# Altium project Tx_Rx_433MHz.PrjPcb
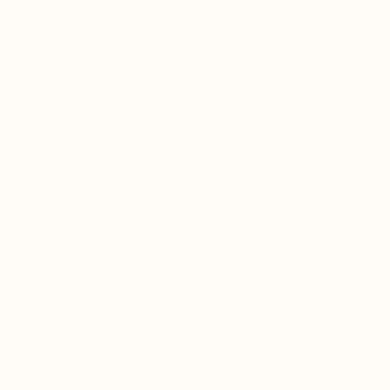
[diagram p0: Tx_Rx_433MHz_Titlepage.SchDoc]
YEAR: 2025; SCH_DOC_VER: 1.0; SCH_AUTHOR: SnLe; PCB_REV: 1A; PCB_ID: 0019-01234; PCB_DOC_VER: 1.0; PCB_AUTHOR: ScSt; PCA_REV: 1A; PCA_NAME: Tx Rx 433MHz Practise Project; PCA_ID: 0029-01234; CLASSIFICATION: Company Confidential
4 sheets, 85 parts. Net scope: global (net labels, ports and power ports of the same name join across sheets).
Board files: Tx_Rx_433MHz.PcbDoc, Tx_Rx_433MHz-Placed.PcbDoc, Tx_Rx_433MHz-Routed.PcbDoc
Sheets:
  Tx_Rx_433MHz_Titlepage.SchDoc
    Top Level = Tx_Rx_433MHz_Block_diagram.SchDoc
      RX = RX.SchDoc
      TX = TX.SchDoc

## Sheet Tx_Rx_433MHz_Titlepage.SchDoc
size A2; SheetNumber: 1; SheetTotal: 4; APPROVED: Yes; Border_Classification: ?; CmpIndex: 0; ENGINEER: KuRe/SnLe; REVIEWED: Yes; REVISION: 2.0; SymIndex: 0; SHEET_SIZE: A2; SHEET02_TITLE: Block Diagram; SHEET03_TITLE: RX; SHEET04_TITLE: TX; SHEET01_TITLE: Title Page; SHEET01_PAGE: 1; SHEET02_PAGE: 2; SHEET03_PAGE: 3; SHEET04_PAGE: 4

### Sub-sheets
Top Level = Tx_Rx_433MHz_Block_diagram.SchDoc: no entries

## Sheet Tx_Rx_433MHz_Block_diagram.SchDoc
size A2; SheetNumber: 1; SheetTotal: 4; APPROVED: Yes; Border_Classification: ?; CmpIndex: 1; ENGINEER: KuRe/SnLe; REVIEWED: Yes; REVISION: 2.0; SymIndex: 1; SHEET_SIZE: A2
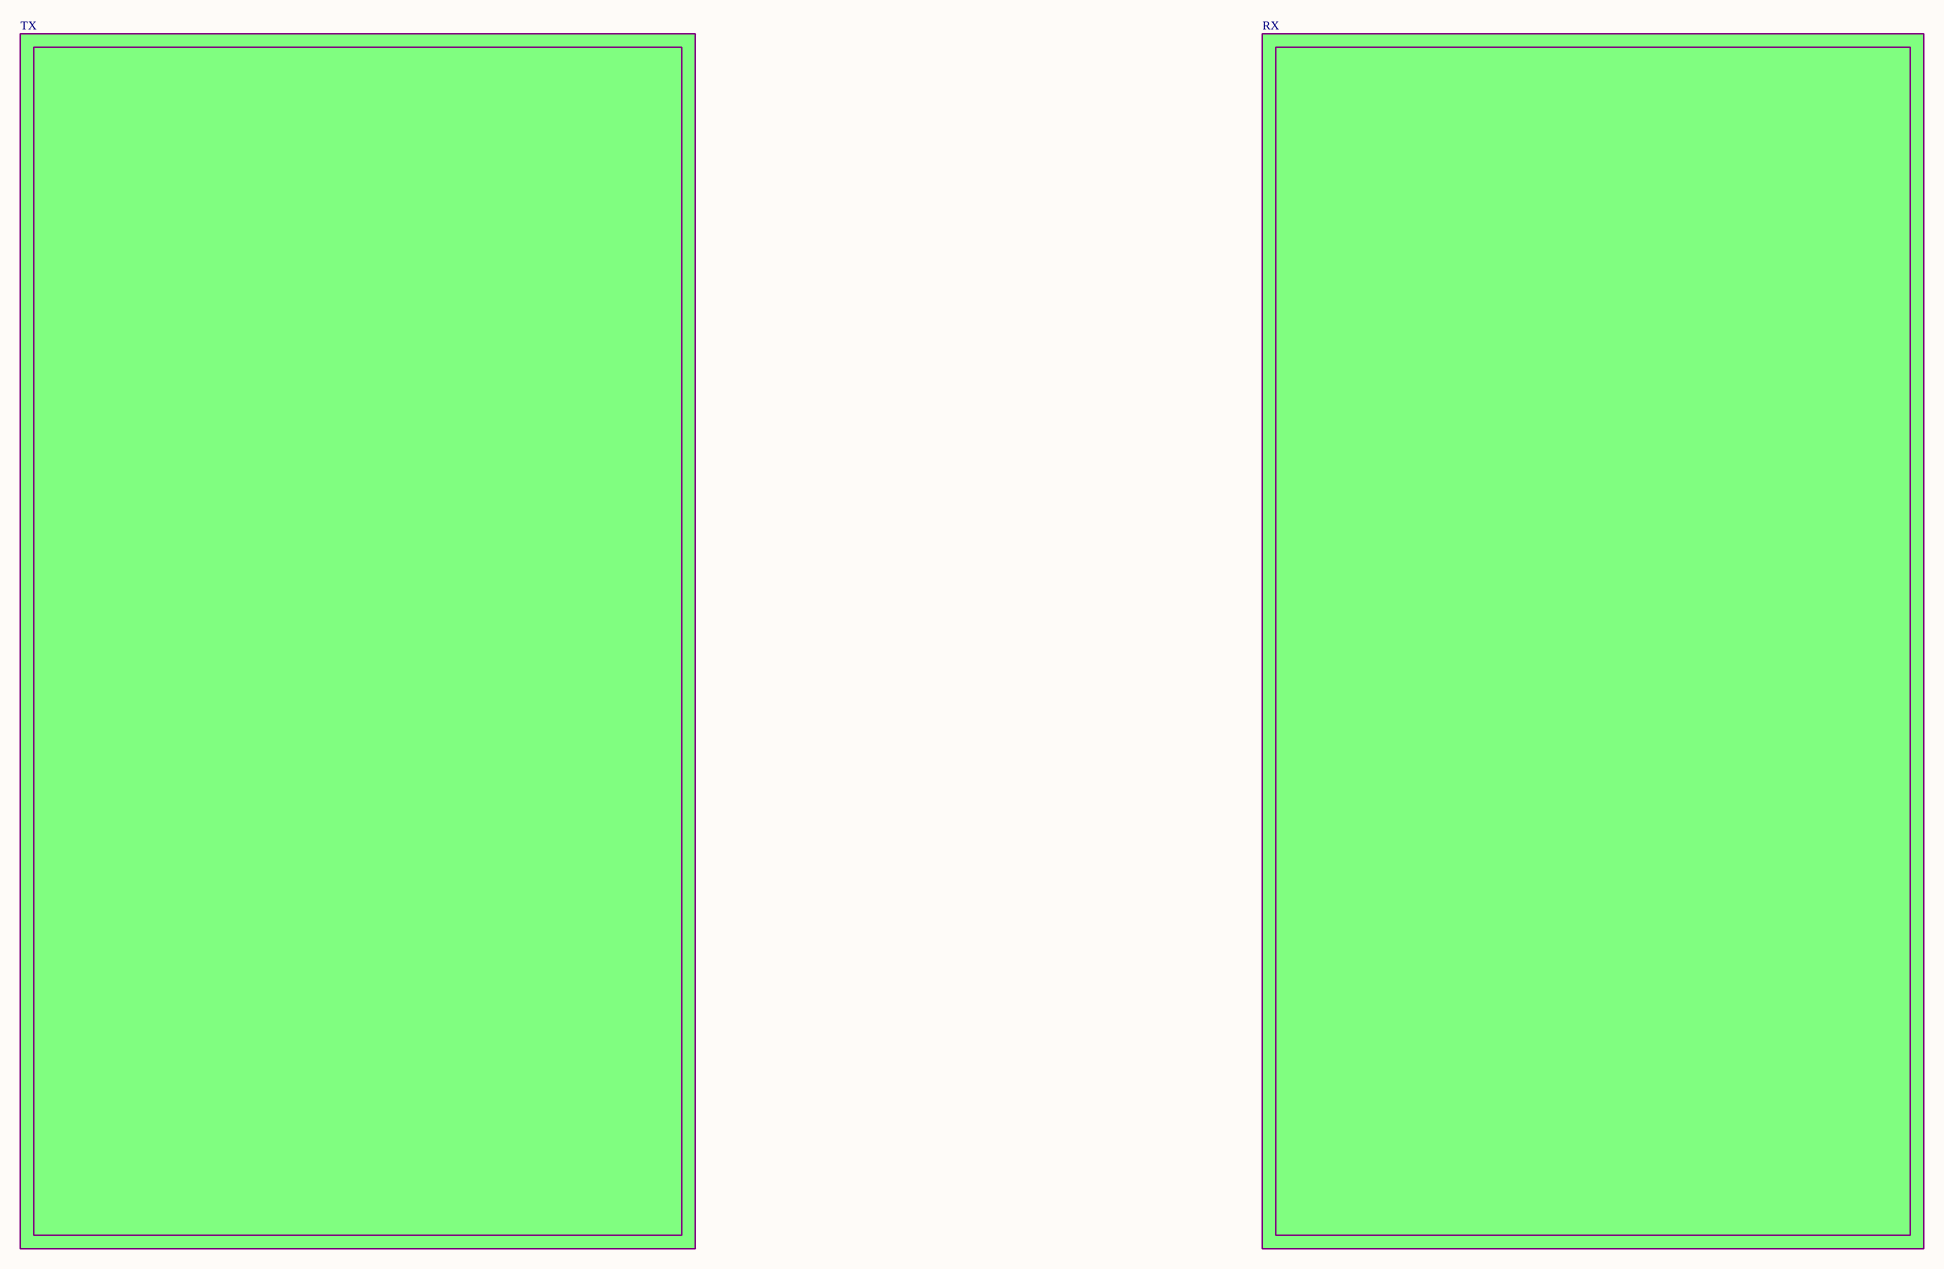
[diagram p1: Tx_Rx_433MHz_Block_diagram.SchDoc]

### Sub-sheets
RX = RX.SchDoc: no entries  | CmpIndex: 3; Name: RX; RefDes Renumber: Refresh; RefDes Start: 200; SymIndex: 6
TX = TX.SchDoc: no entries  | CmpIndex: 2; Name: TX; RefDes Renumber: Refresh; RefDes Start: 100; SymIndex: 4

## Sheet RX.SchDoc
size A2; SheetNumber: 2; SheetTotal: 4; APPROVED: Yes; Border_Classification: ?; CmpIndex: 0; ENGINEER: KuRe/SnLe; REVIEWED: Yes; REVISION: 2.0; SymIndex: 1; SHEET_SIZE: A2
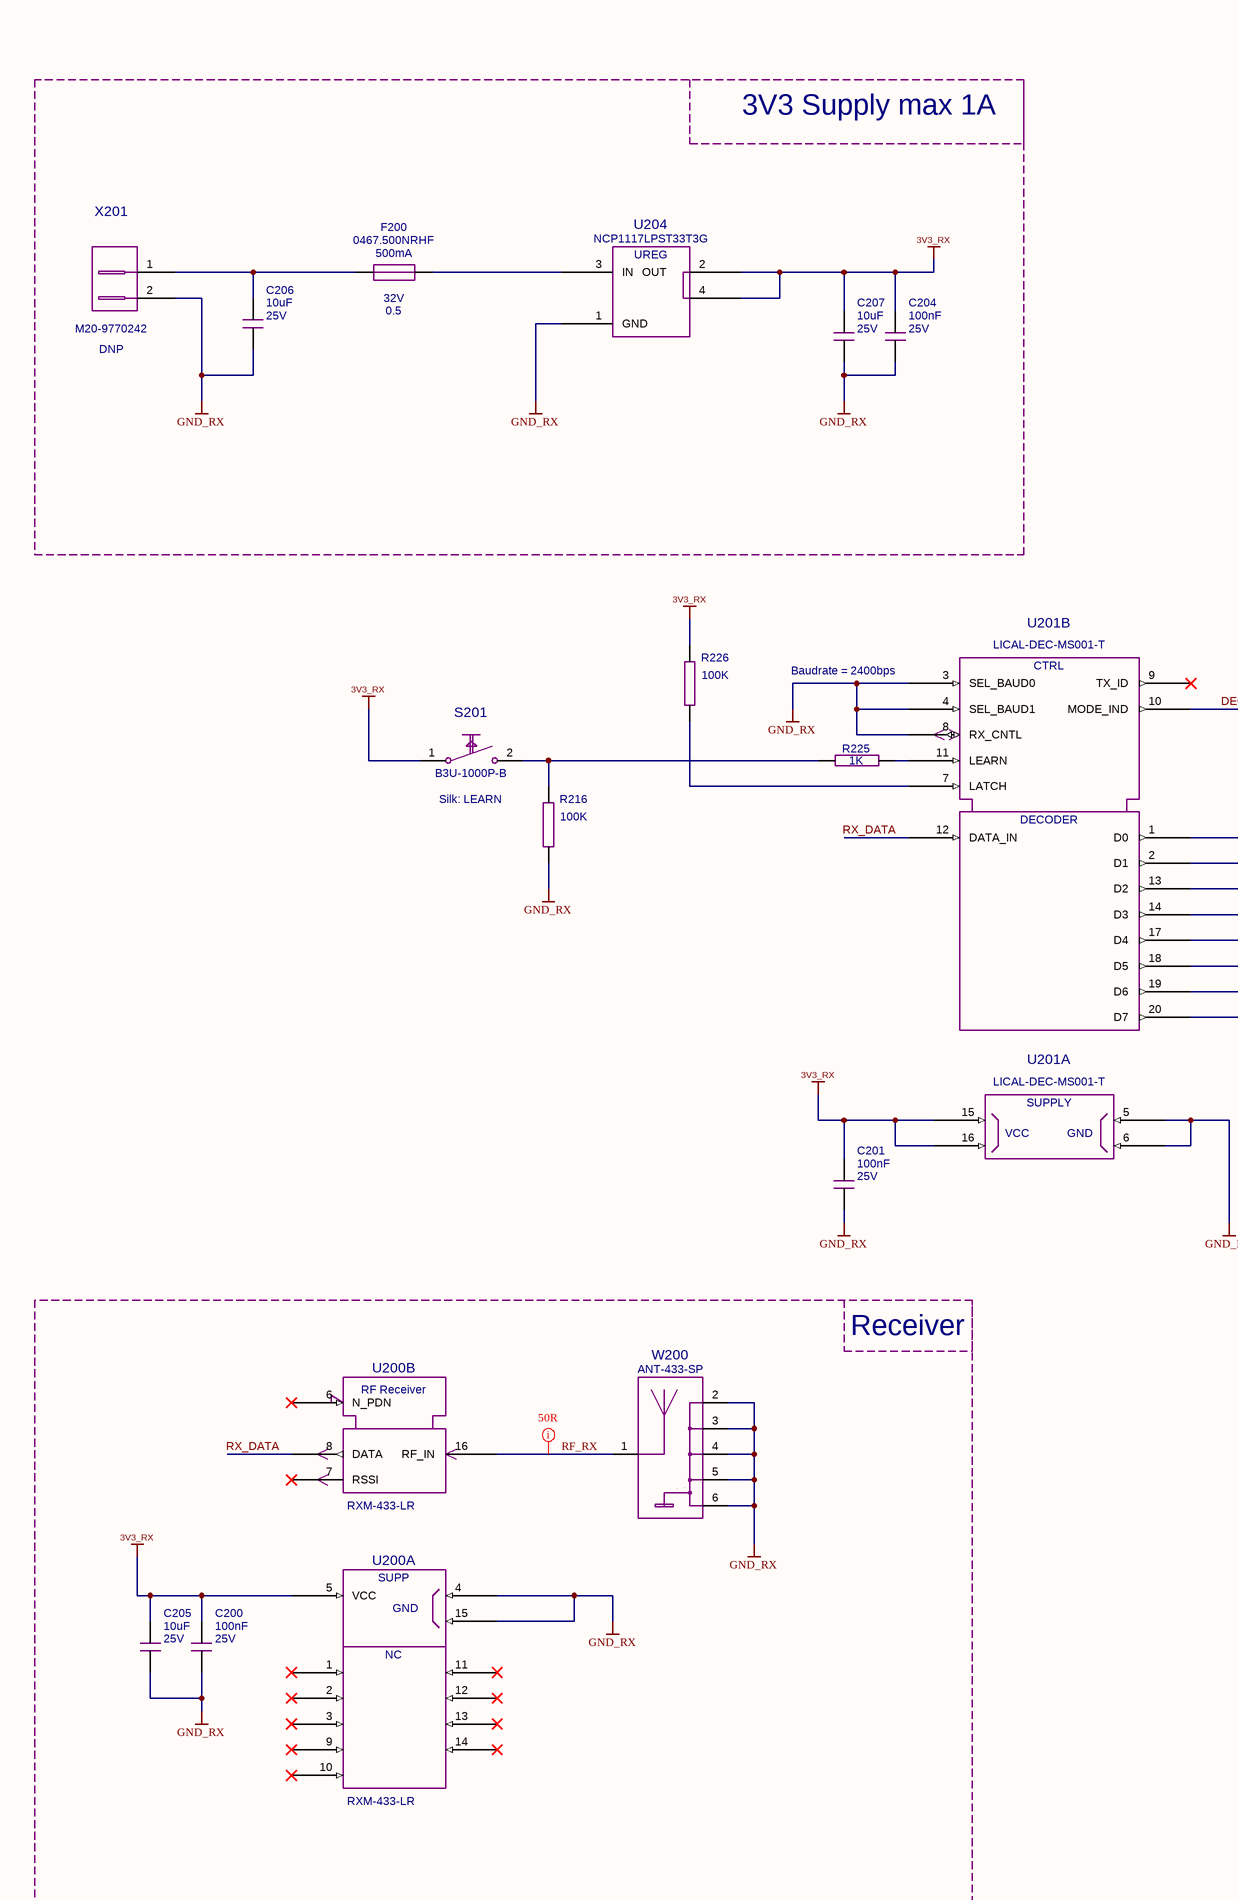
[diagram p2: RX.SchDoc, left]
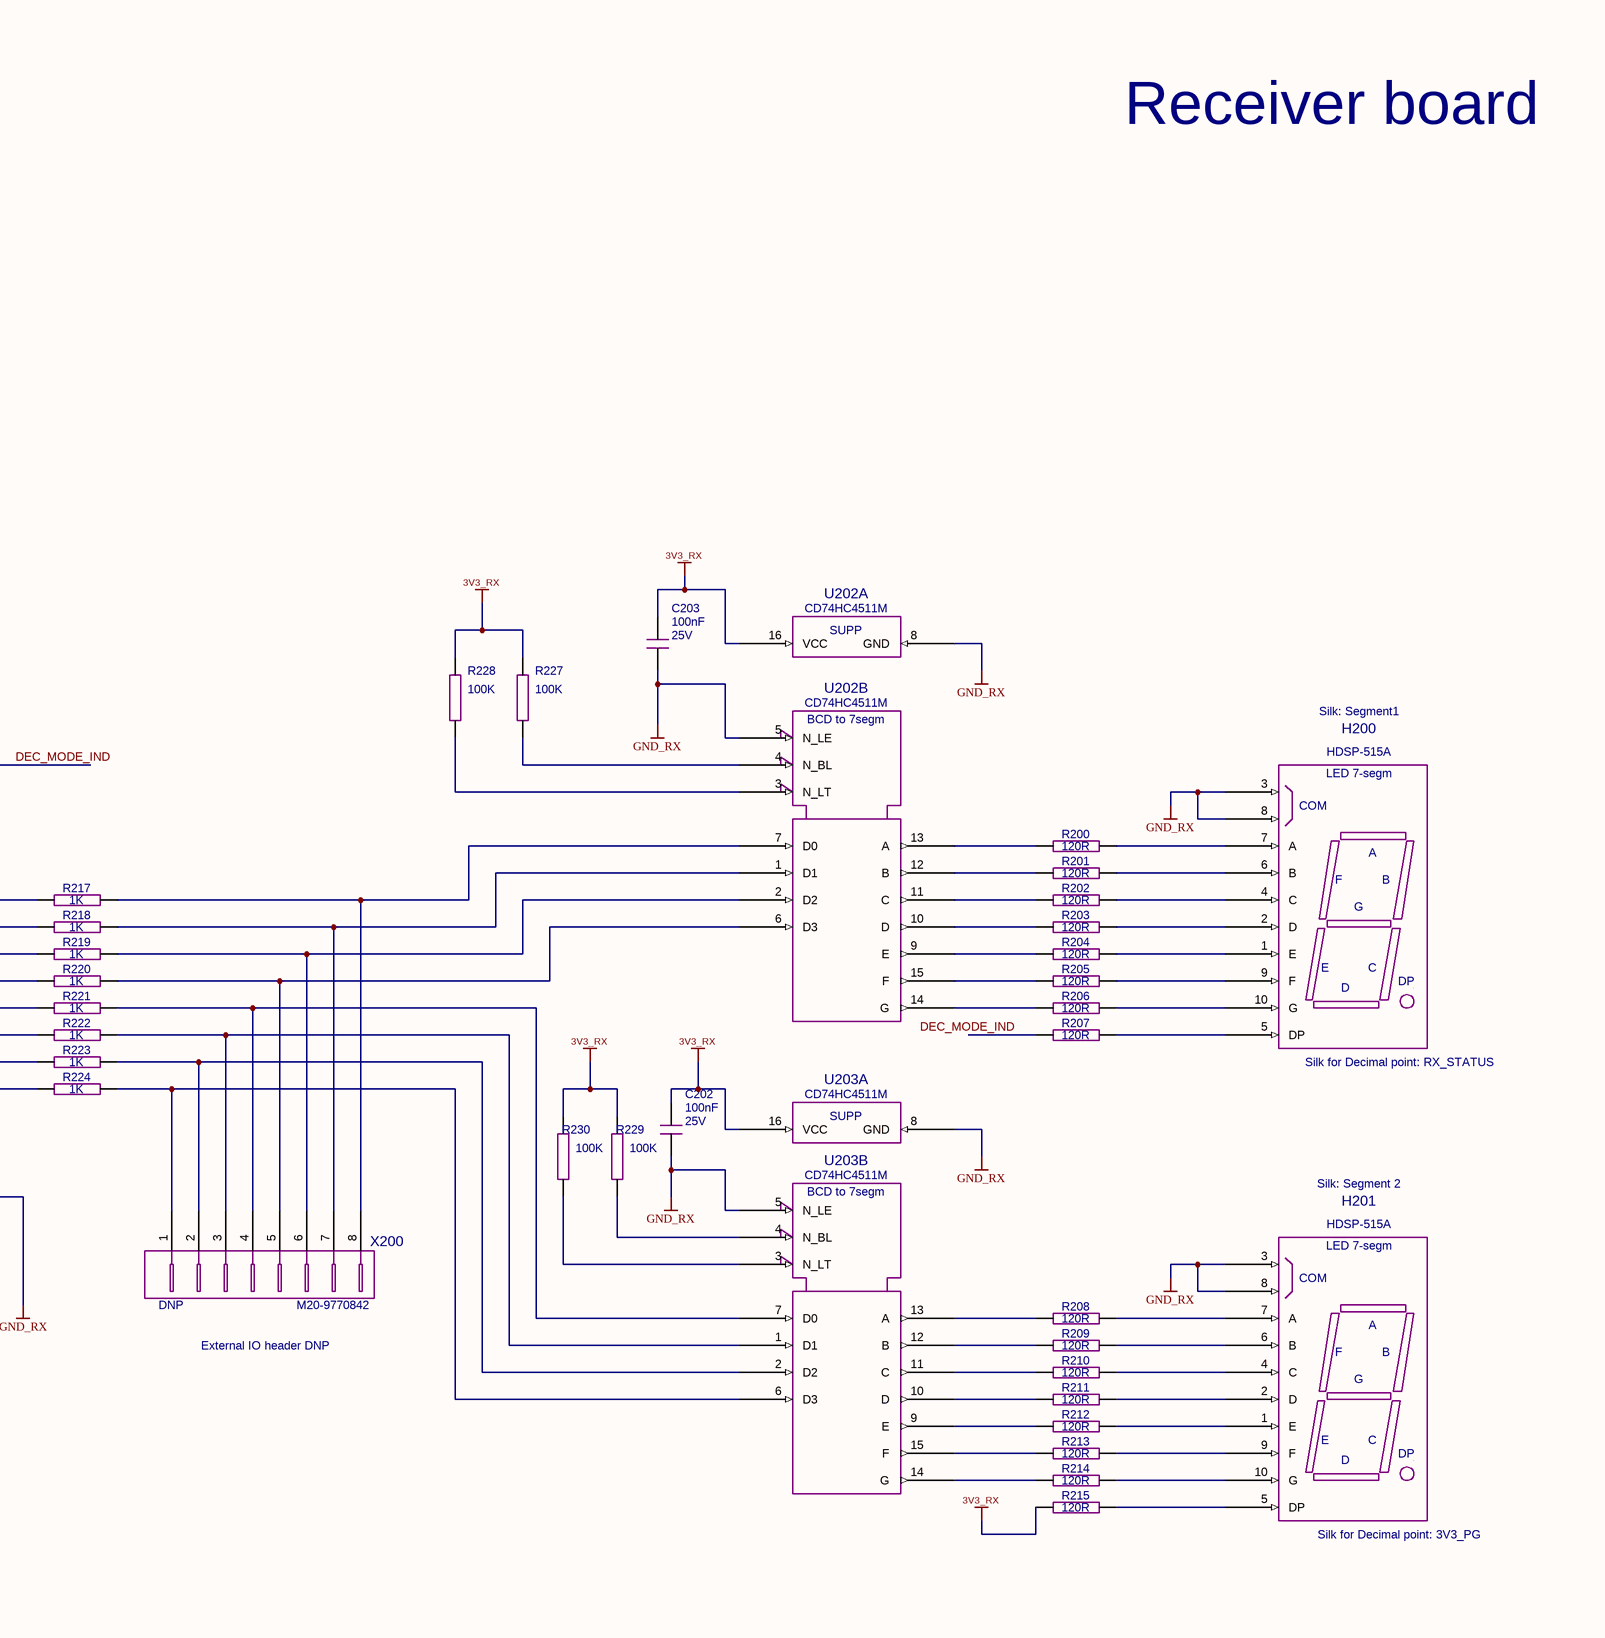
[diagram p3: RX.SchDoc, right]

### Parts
C200  value 100nF  Voltage: 25V  [CAPC1608X90N_0603_GENERIC]  (hidden comment: C_0603_1608X90_GENERIC)
C201  value 100nF  Voltage: 25V  [CAPC1608X90N_0603_GENERIC]  (hidden comment: C_0603_1608X90_GENERIC)
C202  value 100nF  Voltage: 25V  [CAPC1608X90N_0603_GENERIC]  (hidden comment: C_0603_1608X90_GENERIC)
C203  value 100nF  Voltage: 25V  [CAPC1608X90N_0603_GENERIC]  (hidden comment: C_0603_1608X90_GENERIC)
C204  value 100nF  Voltage: 25V  [CAPC1608X90N_0603_GENERIC]  (hidden comment: C_0603_1608X90_GENERIC)
C205  value 10uF  Voltage: 25V  [CAPC3216X190N_1206_GENERIC]  (hidden comment: C_1206_3216X190_GENERIC)
C206  value 10uF  Voltage: 25V  [CAPC2013X140N_AVX]  (hidden comment: 08051C104KAZ2A)
C207  value 10uF  Voltage: 25V  [CAPC2013X140N_AVX]  (hidden comment: 08051C104KAZ2A)
F200  value 500mA  Current: 0.5  MPN: 0467.500NRHF  Voltage: 32V  [RESC1608X60N_0603_GENERIC]  (hidden comment: 0467XXXX)
H200  MPN: HDSP-515A  [BROADCOM_HDSP-5XXX]  (hidden comment: HDSP-5XXX)
H201  MPN: HDSP-515A  [BROADCOM_HDSP-5XXX]  (hidden comment: HDSP-5XXX)
R200  value 120R  [RESC2012X60N_0805_GENERIC]  (hidden comment: R_0805_2012X60_GENERIC)
R201  value 120R  [RESC2012X60N_0805_GENERIC]  (hidden comment: R_0805_2012X60_GENERIC)
R202  value 120R  [RESC2012X60N_0805_GENERIC]  (hidden comment: R_0805_2012X60_GENERIC)
R203  value 120R  [RESC2012X60N_0805_GENERIC]  (hidden comment: R_0805_2012X60_GENERIC)
R204  value 120R  [RESC2012X60N_0805_GENERIC]  (hidden comment: R_0805_2012X60_GENERIC)
R205  value 120R  [RESC2012X60N_0805_GENERIC]  (hidden comment: R_0805_2012X60_GENERIC)
R206  value 120R  [RESC2012X60N_0805_GENERIC]  (hidden comment: R_0805_2012X60_GENERIC)
R207  value 120R  [RESC2012X60N_0805_GENERIC]  (hidden comment: R_0805_2012X60_GENERIC)
R208  value 120R  [RESC2012X60N_0805_GENERIC]  (hidden comment: R_0805_2012X60_GENERIC)
R209  value 120R  [RESC2012X60N_0805_GENERIC]  (hidden comment: R_0805_2012X60_GENERIC)
R210  value 120R  [RESC2012X60N_0805_GENERIC]  (hidden comment: R_0805_2012X60_GENERIC)
R211  value 120R  [RESC2012X60N_0805_GENERIC]  (hidden comment: R_0805_2012X60_GENERIC)
R212  value 120R  [RESC2012X60N_0805_GENERIC]  (hidden comment: R_0805_2012X60_GENERIC)
R213  value 120R  [RESC2012X60N_0805_GENERIC]  (hidden comment: R_0805_2012X60_GENERIC)
R214  value 120R  [RESC2012X60N_0805_GENERIC]  (hidden comment: R_0805_2012X60_GENERIC)
R215  value 120R  [RESC2012X60N_0805_GENERIC]  (hidden comment: R_0805_2012X60_GENERIC)
R216  value 100K  [RESC2012X60N_0805_GENERIC]  (hidden comment: R_0805_2012X60_GENERIC)
R217  value 1K  [RESC2012X60N_0805_GENERIC]  (hidden comment: R_0805_2012X60_GENERIC)
R218  value 1K  [RESC2012X60N_0805_GENERIC]  (hidden comment: R_0805_2012X60_GENERIC)
R219  value 1K  [RESC2012X60N_0805_GENERIC]  (hidden comment: R_0805_2012X60_GENERIC)
R220  value 1K  [RESC2012X60N_0805_GENERIC]  (hidden comment: R_0805_2012X60_GENERIC)
R221  value 1K  [RESC2012X60N_0805_GENERIC]  (hidden comment: R_0805_2012X60_GENERIC)
R222  value 1K  [RESC2012X60N_0805_GENERIC]  (hidden comment: R_0805_2012X60_GENERIC)
R223  value 1K  [RESC2012X60N_0805_GENERIC]  (hidden comment: R_0805_2012X60_GENERIC)
R224  value 1K  [RESC2012X60N_0805_GENERIC]  (hidden comment: R_0805_2012X60_GENERIC)
R225  value 1K  [RESC2012X60N_0805_GENERIC]  (hidden comment: R_0805_2012X60_GENERIC)
R226  value 100K  [RESC2012X60N_0805_GENERIC]  (hidden comment: R_0805_2012X60_GENERIC)
R227  value 100K  [RESC2012X60N_0805_GENERIC]  (hidden comment: R_0805_2012X60_GENERIC)
R228  value 100K  [RESC2012X60N_0805_GENERIC]  (hidden comment: R_0805_2012X60_GENERIC)
R229  value 100K  [RESC2012X60N_0805_GENERIC]  (hidden comment: R_0805_2012X60_GENERIC)
R230  value 100K  [RESC2012X60N_0805_GENERIC]  (hidden comment: R_0805_2012X60_GENERIC)
S201  MPN: B3U-1000P-B  [OMRON_B3U_1000P_B]  (hidden comment: B3U_1000P_B)
U200  RXM-433-LR  [LINX_RXM-433-LR]  (parts A,B of 2)
U201  MPN: LICAL-DEC-MS001-T  [SOP65P780X200-20N]  (hidden comment: LICAL-DEC-MS001)  (parts A,B of 2)
U202  CD74HC4511M  [SOIC127P600X175-16N]  (parts A,B of 2)
U203  CD74HC4511M  [SOIC127P600X175-16N]  (parts A,B of 2)
U204  MPN: NCP1117LPST33T3G  [SOT230P700X180-4N]  (hidden comment: LM1117MPX)
W200  ANT-433-SP  [LINX_ANT-433-SP]
X200  MPN: M20-9770842  Place: DNP  [HARWIN_M20_9770842]  (hidden comment: M20_9770842)
X201  MPN: M20-9770242  Place: DNP  [HARWIN_M20_9770242]  (hidden comment: M20_9770242)

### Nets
3V3_RX: C200.1(P) C201.1(P) C202.1(P) C203.1(P) C204.1(P) C205.1(P) C207.1(P) R215.1(P) R226.2(M) R227.2(M) R228.2(M) R229.2(M) R230.2(M) S201.1(S1) U200.5(VCC) U201.15(VCC1) U201.16(VCC2) U202.16(VCC) U203.16(VCC) U204.2(OUT) U204.4(TAB)
GND_RX: C200.2(M) C201.2(M) C202.2(M) C203.2(M) C204.2(M) C205.2(M) C206.2(M) C207.2(M) H200.3(COM1) H200.8(COM2) H201.3(COM1) H201.8(COM2) R216.1(P) U200.4(GND1) U200.15(GND2) U201.3(SEL_BAUD0) U201.4(SEL_BAUD1) U201.5(GND1) U201.6(GND2) U201.8(RX_CNTL) U202.5(N_LE) U202.8(GND) U203.5(N_LE) U203.8(GND) U204.1(GND) W200.2(GND1) W200.3(GND2) W200.4(GND3) W200.5(GND4) W200.6(GND5) X201.2(P2)
DEC_MODE_IND: R207.1(P) U201.10(MODE_IND)
RF_RX: U200.16(RF_IN) W200.1(ANT)
RX_DATA: U200.8(DATA) U201.12(DATA_IN)
NetC206_1: C206.1(P) F200.1(A) X201.1(P1)
NetF200_2: F200.2(B) U204.3(IN)
NetH200_1: H200.1(E) R204.2(M)
NetH200_2: H200.2(D) R203.2(M)
NetH200_4: H200.4(C) R202.2(M)
NetH200_5: H200.5(DP) R207.2(M)
NetH200_6: H200.6(B) R201.2(M)
NetH200_7: H200.7(A) R200.2(M)
NetH200_9: H200.9(F) R205.2(M)
NetH200_10: H200.10(G) R206.2(M)
NetH201_1: H201.1(E) R212.2(M)
NetH201_2: H201.2(D) R211.2(M)
NetH201_4: H201.4(C) R210.2(M)
NetH201_5: H201.5(DP) R215.2(M)
NetH201_6: H201.6(B) R209.2(M)
NetH201_7: H201.7(A) R208.2(M)
NetH201_9: H201.9(F) R213.2(M)
NetH201_10: H201.10(G) R214.2(M)
NetR200_1: R200.1(P) U202.13(A)
NetR201_1: R201.1(P) U202.12(B)
NetR202_1: R202.1(P) U202.11(C)
NetR203_1: R203.1(P) U202.10(D)
NetR204_1: R204.1(P) U202.9(E)
NetR205_1: R205.1(P) U202.15(F)
NetR206_1: R206.1(P) U202.14(G)
NetR208_1: R208.1(P) U203.13(A)
NetR209_1: R209.1(P) U203.12(B)
NetR210_1: R210.1(P) U203.11(C)
NetR211_1: R211.1(P) U203.10(D)
NetR212_1: R212.1(P) U203.9(E)
NetR213_1: R213.1(P) U203.15(F)
NetR214_1: R214.1(P) U203.14(G)
NetR216_2: R216.2(M) R225.1(P) S201.2(S2)
NetR217_1: R217.1(P) U201.1(D0)
NetR217_2: R217.2(M) U202.7(D0) X200.8(P8)
NetR218_1: R218.1(P) U201.2(D1)
NetR218_2: R218.2(M) U202.1(D1) X200.7(P7)
NetR219_1: R219.1(P) U201.13(D2)
NetR219_2: R219.2(M) U202.2(D2) X200.6(P6)
NetR220_1: R220.1(P) U201.14(D3)
NetR220_2: R220.2(M) U202.6(D3) X200.5(P5)
NetR221_1: R221.1(P) U201.17(D4)
NetR221_2: R221.2(M) U203.7(D0) X200.4(P4)
NetR222_1: R222.1(P) U201.18(D5)
NetR222_2: R222.2(M) U203.1(D1) X200.3(P3)
NetR223_1: R223.1(P) U201.19(D6)
NetR223_2: R223.2(M) U203.2(D2) X200.2(P2)
NetR224_1: R224.1(P) U201.20(D7)
NetR224_2: R224.2(M) U203.6(D3) X200.1(P1)
NetR225_2: R225.2(M) U201.11(LEARN)
NetR226_1: R226.1(P) U201.7(LATCH)
NetR227_1: R227.1(P) U202.4(N_BL)
NetR228_1: R228.1(P) U202.3(N_LT)
NetR229_1: R229.1(P) U203.4(N_BL)
NetR230_1: R230.1(P) U203.3(N_LT)

Not connected (* = marked no-connect by the designer): U200 1(NC1)* 2(NC2)* 3(NC3)* 6(N_PDN)* 7(RSSI)* 9(NC4)* 10(NC5)* 11(NC6)* 12(NC7)* 13(NC8)* 14(NC9)*; U201 9(TX_ID)*

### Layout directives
net class 50R: RF_RX

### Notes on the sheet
- 3V3 Supply max 1A
- Receiver board
- Baudrate = 2400bps
- Silk: Segment1
- Silk: LEARN
- (near H200) Silk for Decimal point: RX_STATUS
- Silk: Segment 2
- External IO header DNP
- Receiver
- (near H201) Silk for Decimal point: 3V3_PG

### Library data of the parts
C200 = C_0603_1608X90_GENERIC: 100nF 25V 10%; Manufacturer: MURATA; MPN: GRM188R71E104KA01D; Part Name: Ceramic chip capacitor 0603-1608x90, generic; Parts: 1; Capacitance: 100000; CmpIndex: 30; Dielectric: X7R; DXDB_LIBNAME: Capacitor; Level: STD; Ref Designator: C200; SymIndex: 23; Tolerance: 10; Type: Ceramic; Valid: -1
C201 = C_0603_1608X90_GENERIC: 100nF 25V 10%; Manufacturer: MURATA; MPN: GRM188R71E104KA01D; Part Name: Ceramic chip capacitor 0603-1608x90, generic; Parts: 1; Capacitance: 100000; CmpIndex: 52; Dielectric: X7R; DXDB_LIBNAME: Capacitor; Level: STD; Ref Designator: C201; SymIndex: 23; Tolerance: 10; Type: Ceramic; Valid: -1
C202 = C_0603_1608X90_GENERIC: 100nF 25V 10%; Manufacturer: MURATA; MPN: GRM188R71E104KA01D; Part Name: Ceramic chip capacitor 0603-1608x90, generic; Parts: 1; Capacitance: 100000; CmpIndex: 80; Dielectric: X7R; DXDB_LIBNAME: Capacitor; Level: STD; Ref Designator: C202; SymIndex: 23; Tolerance: 10; Type: Ceramic; Valid: -1
C203 = C_0603_1608X90_GENERIC: 100nF 25V 10%; Manufacturer: MURATA; MPN: GRM188R71E104KA01D; Part Name: Ceramic chip capacitor 0603-1608x90, generic; Parts: 1; Capacitance: 100000; CmpIndex: 81; Dielectric: X7R; DXDB_LIBNAME: Capacitor; Level: STD; Ref Designator: C203; SymIndex: 23; Tolerance: 10; Type: Ceramic; Valid: -1
C204 = C_0603_1608X90_GENERIC: 100nF 25V 10%; Manufacturer: MURATA; MPN: GRM188R71E104KA01D; Part Name: Ceramic chip capacitor 0603-1608x90, generic; Parts: 1; Capacitance: 100000; CmpIndex: 16; Dielectric: X7R; DXDB_LIBNAME: Capacitor; Level: STD; Ref Designator: C204; SymIndex: 23; Tolerance: 10; Type: Ceramic; Valid: -1
C205 = C_1206_3216X190_GENERIC: 10uF 25V 10%; Manufacturer: AVX; MPN: 12063C106KAT2A; Part Name: Cheramic chip capacitor 1206-3216x190, generic; Parts: 1; Capacitance: 10000000; CmpIndex: 33; Dielectric: X7R; DXDB_LIBNAME: Capacitor; Level: STD; Max Temp: +125; Min Temp: -55; Ref Designator: C205; SymIndex: 23; Tolerance: 10; Type: Ceramic; Valid: -1
C206 = 08051C104KAZ2A: 10uF 25V 10%; Manufacturer: AVX; MPN: 08053D106KAT2A; Part Name: 0805 chip 100nF 10% 100V X7R; Parts: 1; Capacitance: 10000000; CmpIndex: 12; Dielectric: X5R; DXDB_LIBNAME: Capacitor; Level: STD; Ref Designator: C206; SymIndex: 23; Tolerance: 10; Type: Ceramic; Valid: 0
C207 = 08051C104KAZ2A: 10uF 25V 10%; Manufacturer: AVX; MPN: 08053D106KAT2A; Part Name: 0805 chip 100nF 10% 100V X7R; Parts: 1; Capacitance: 10000000; CmpIndex: 15; Dielectric: X5R; DXDB_LIBNAME: Capacitor; Level: STD; Ref Designator: C207; SymIndex: 23; Tolerance: 10; Type: Ceramic; Valid: 0
F200 = 0467XXXX: Thin film 0603 fuse very fast acting; Manufacturer: LITTELFUSE; Part Name: Thin film 0603 very fast acting; CmpIndex: 18; Level: STD; Max Temp: +90; Min Temp: -55; Ref Designator: F200; SymIndex: 25; Valid: -1
H200 = HDSP-5XXX: 7 Segment Display Module Red, 1,85V, 20mA. THT; Manufacturer: BROADCOM; Part Name: Single Digit LED Numeric Display, Blue color; CmpIndex: 5; DXDB_LIBNAME: Optical; Level: STD; Max Temp: 85; Min Temp: -25; Ref Designator: H200; SymIndex: 14; Valid: 0
H201 = HDSP-5XXX: 7 Segment Display Module Red, 1,85V, 20mA. THT; Manufacturer: BROADCOM; Part Name: Single Digit LED Numeric Display, Blue color; CmpIndex: 66; DXDB_LIBNAME: Optical; Level: STD; Max Temp: 85; Min Temp: -25; Ref Designator: H201; SymIndex: 14; Valid: 0
R200 = R_0805_2012X60_GENERIC: 0.125W 5% 120R 50V; Manufacturer: YAGEO; MPN: RC0805JR-07120RL; Part Name: resistor_0805-2012x60 generic; CmpIndex: 40; DXDB_LIBNAME: Resistor_0805; Level: STD; Ref Designator: R200; SymIndex: 28; Valid: -1
R201 = R_0805_2012X60_GENERIC: 0.125W 5% 120R 50V; Manufacturer: YAGEO; MPN: RC0805JR-07120RL; Part Name: resistor_0805-2012x60 generic; CmpIndex: 41; DXDB_LIBNAME: Resistor_0805; Level: STD; Ref Designator: R201; SymIndex: 28; Valid: -1
R202 = R_0805_2012X60_GENERIC: 0.125W 5% 120R 50V; Manufacturer: YAGEO; MPN: RC0805JR-07120RL; Part Name: resistor_0805-2012x60 generic; CmpIndex: 60; DXDB_LIBNAME: Resistor_0805; Level: STD; Ref Designator: R202; SymIndex: 28; Valid: -1
R203 = R_0805_2012X60_GENERIC: 0.125W 5% 120R 50V; Manufacturer: YAGEO; MPN: RC0805JR-07120RL; Part Name: resistor_0805-2012x60 generic; CmpIndex: 61; DXDB_LIBNAME: Resistor_0805; Level: STD; Ref Designator: R203; SymIndex: 28; Valid: -1
R204 = R_0805_2012X60_GENERIC: 0.125W 5% 120R 50V; Manufacturer: YAGEO; MPN: RC0805JR-07120RL; Part Name: resistor_0805-2012x60 generic; CmpIndex: 62; DXDB_LIBNAME: Resistor_0805; Level: STD; Ref Designator: R204; SymIndex: 28; Valid: -1
R205 = R_0805_2012X60_GENERIC: 0.125W 5% 120R 50V; Manufacturer: YAGEO; MPN: RC0805JR-07120RL; Part Name: resistor_0805-2012x60 generic; CmpIndex: 63; DXDB_LIBNAME: Resistor_0805; Level: STD; Ref Designator: R205; SymIndex: 28; Valid: -1
R206 = R_0805_2012X60_GENERIC: 0.125W 5% 120R 50V; Manufacturer: YAGEO; MPN: RC0805JR-07120RL; Part Name: resistor_0805-2012x60 generic; CmpIndex: 64; DXDB_LIBNAME: Resistor_0805; Level: STD; Ref Designator: R206; SymIndex: 28; Valid: -1
R207 = R_0805_2012X60_GENERIC: 0.125W 5% 120R 50V; Manufacturer: YAGEO; MPN: RC0805JR-07120RL; Part Name: resistor_0805-2012x60 generic; CmpIndex: 73; DXDB_LIBNAME: Resistor_0805; Level: STD; Ref Designator: R207; SymIndex: 28; Valid: -1
R208 = R_0805_2012X60_GENERIC: 0.125W 5% 120R 50V; Manufacturer: YAGEO; MPN: RC0805JR-07120RL; Part Name: resistor_0805-2012x60 generic; CmpIndex: 6; DXDB_LIBNAME: Resistor_0805; Level: STD; Ref Designator: R208; SymIndex: 28; Valid: -1
R209 = R_0805_2012X60_GENERIC: 0.125W 5% 120R 50V; Manufacturer: YAGEO; MPN: RC0805JR-07120RL; Part Name: resistor_0805-2012x60 generic; CmpIndex: 67; DXDB_LIBNAME: Resistor_0805; Level: STD; Ref Designator: R209; SymIndex: 28; Valid: -1
R210 = R_0805_2012X60_GENERIC: 0.125W 5% 120R 50V; Manufacturer: YAGEO; MPN: RC0805JR-07120RL; Part Name: resistor_0805-2012x60 generic; CmpIndex: 68; DXDB_LIBNAME: Resistor_0805; Level: STD; Ref Designator: R210; SymIndex: 28; Valid: -1
R211 = R_0805_2012X60_GENERIC: 0.125W 5% 120R 50V; Manufacturer: YAGEO; MPN: RC0805JR-07120RL; Part Name: resistor_0805-2012x60 generic; CmpIndex: 69; DXDB_LIBNAME: Resistor_0805; Level: STD; Ref Designator: R211; SymIndex: 28; Valid: -1
R212 = R_0805_2012X60_GENERIC: 0.125W 5% 120R 50V; Manufacturer: YAGEO; MPN: RC0805JR-07120RL; Part Name: resistor_0805-2012x60 generic; CmpIndex: 70; DXDB_LIBNAME: Resistor_0805; Level: STD; Ref Designator: R212; SymIndex: 28; Valid: -1
R213 = R_0805_2012X60_GENERIC: 0.125W 5% 120R 50V; Manufacturer: YAGEO; MPN: RC0805JR-07120RL; Part Name: resistor_0805-2012x60 generic; CmpIndex: 71; DXDB_LIBNAME: Resistor_0805; Level: STD; Ref Designator: R213; SymIndex: 28; Valid: -1
R214 = R_0805_2012X60_GENERIC: 0.125W 5% 120R 50V; Manufacturer: YAGEO; MPN: RC0805JR-07120RL; Part Name: resistor_0805-2012x60 generic; CmpIndex: 72; DXDB_LIBNAME: Resistor_0805; Level: STD; Ref Designator: R214; SymIndex: 28; Valid: -1
R215 = R_0805_2012X60_GENERIC: 0.125W 5% 120R 50V; Manufacturer: YAGEO; MPN: RC0805JR-07120RL; Part Name: resistor_0805-2012x60 generic; CmpIndex: 74; DXDB_LIBNAME: Resistor_0805; Level: STD; Ref Designator: R215; SymIndex: 28; Valid: -1
R216 = R_0805_2012X60_GENERIC: 0.125W 5% 100K 50V; Manufacturer: YAGEO; MPN: RC0805JR-07100KL; Part Name: resistor_0805-2012x60 generic; CmpIndex: 38; DXDB_LIBNAME: Resistor_0805; Level: STD; Ref Designator: R216; SymIndex: 28; Valid: -1
R217 = R_0805_2012X60_GENERIC: Resistor_1K_1%_0805; Manufacturer: MULTICOMP; MPN: MCPWR05FTEW1001; Part Name: resistor_0805-2012x60 generic; CmpIndex: 43; DXDB_LIBNAME: Resistor_0805; Level: STD; Ref Designator: R217; SymIndex: 28; Tolerance: 1%; Valid: -1
R218 = R_0805_2012X60_GENERIC: Resistor_1K_1%_0805; Manufacturer: MULTICOMP; MPN: MCPWR05FTEW1001; Part Name: resistor_0805-2012x60 generic; CmpIndex: 44; DXDB_LIBNAME: Resistor_0805; Level: STD; Ref Designator: R218; SymIndex: 28; Tolerance: 1%; Valid: -1
R219 = R_0805_2012X60_GENERIC: Resistor_1K_1%_0805; Manufacturer: MULTICOMP; MPN: MCPWR05FTEW1001; Part Name: resistor_0805-2012x60 generic; CmpIndex: 45; DXDB_LIBNAME: Resistor_0805; Level: STD; Ref Designator: R219; SymIndex: 28; Tolerance: 1%; Valid: -1
R220 = R_0805_2012X60_GENERIC: Resistor_1K_1%_0805; Manufacturer: MULTICOMP; MPN: MCPWR05FTEW1001; Part Name: resistor_0805-2012x60 generic; CmpIndex: 46; DXDB_LIBNAME: Resistor_0805; Level: STD; Ref Designator: R220; SymIndex: 28; Tolerance: 1%; Valid: -1
R221 = R_0805_2012X60_GENERIC: Resistor_1K_1%_0805; Manufacturer: MULTICOMP; MPN: MCPWR05FTEW1001; Part Name: resistor_0805-2012x60 generic; CmpIndex: 47; DXDB_LIBNAME: Resistor_0805; Level: STD; Ref Designator: R221; SymIndex: 28; Tolerance: 1%; Valid: -1
R222 = R_0805_2012X60_GENERIC: Resistor_1K_1%_0805; Manufacturer: MULTICOMP; MPN: MCPWR05FTEW1001; Part Name: resistor_0805-2012x60 generic; CmpIndex: 48; DXDB_LIBNAME: Resistor_0805; Level: STD; Ref Designator: R222; SymIndex: 28; Tolerance: 1%; Valid: -1
R223 = R_0805_2012X60_GENERIC: Resistor_1K_1%_0805; Manufacturer: MULTICOMP; MPN: MCPWR05FTEW1001; Part Name: resistor_0805-2012x60 generic; CmpIndex: 49; DXDB_LIBNAME: Resistor_0805; Level: STD; Ref Designator: R223; SymIndex: 28; Tolerance: 1%; Valid: -1
R224 = R_0805_2012X60_GENERIC: Resistor_1K_1%_0805; Manufacturer: MULTICOMP; MPN: MCPWR05FTEW1001; Part Name: resistor_0805-2012x60 generic; CmpIndex: 50; DXDB_LIBNAME: Resistor_0805; Level: STD; Ref Designator: R224; SymIndex: 28; Tolerance: 1%; Valid: -1
R225 = R_0805_2012X60_GENERIC: Resistor_1K_1%_0805; Manufacturer: MULTICOMP; MPN: MCPWR05FTEW1001; Part Name: resistor_0805-2012x60 generic; CmpIndex: 35; DXDB_LIBNAME: Resistor_0805; Level: STD; Ref Designator: R225; SymIndex: 28; Tolerance: 1%; Valid: -1
R226 = R_0805_2012X60_GENERIC: 0.125W 5% 100K 50V; Manufacturer: YAGEO; MPN: RC0805JR-07100KL; Part Name: resistor_0805-2012x60 generic; CmpIndex: 57; DXDB_LIBNAME: Resistor_0805; Level: STD; Ref Designator: R226; SymIndex: 28; Valid: -1
R227 = R_0805_2012X60_GENERIC: 0.125W 5% 100K 50V; Manufacturer: YAGEO; MPN: RC0805JR-07100KL; Part Name: resistor_0805-2012x60 generic; CmpIndex: 86; DXDB_LIBNAME: Resistor_0805; Level: STD; Ref Designator: R227; SymIndex: 28; Valid: -1
R228 = R_0805_2012X60_GENERIC: 0.125W 5% 100K 50V; Manufacturer: YAGEO; MPN: RC0805JR-07100KL; Part Name: resistor_0805-2012x60 generic; CmpIndex: 87; DXDB_LIBNAME: Resistor_0805; Level: STD; Ref Designator: R228; SymIndex: 28; Valid: -1
R229 = R_0805_2012X60_GENERIC: 0.125W 5% 100K 50V; Manufacturer: YAGEO; MPN: RC0805JR-07100KL; Part Name: resistor_0805-2012x60 generic; CmpIndex: 89; DXDB_LIBNAME: Resistor_0805; Level: STD; Ref Designator: R229; SymIndex: 28; Valid: -1
R230 = R_0805_2012X60_GENERIC: 0.125W 5% 100K 50V; Manufacturer: YAGEO; MPN: RC0805JR-07100KL; Part Name: resistor_0805-2012x60 generic; CmpIndex: 91; DXDB_LIBNAME: Resistor_0805; Level: STD; Ref Designator: R230; SymIndex: 28; Valid: -1
S201 = B3U_1000P_B: Ultra-small Tactile Switch; Manufacturer: OMRON; CmpIndex: 1; Contacts: 2; Level: STD; Max Temp: 0; Ref Designator: S201; SymIndex: 8
U200 = RXM-433-LR: LR Series Receiver, Low Voltage, Low Power; Manufacturer: Linx Technologies; CmpIndex: 4; DXDB_LIBNAME: Module; Level: STD; Max Temp: 70; Min Temp: -40; Quality: Q2; Ref Designator: U200; SymIndex: 13; Valid: 0
U201 = LICAL-DEC-MS001: MS Series Remote Controler Decoder, Low Voltage, Low Power; Manufacturer: LINX TECHNOLOGIES; CmpIndex: 8; DXDB_LIBNAME: IC Generic; Level: STD; Max Temp: 85; Min Temp: -40; Ref Designator: U201; SymIndex: 16; Valid: 0
U202 = CD74HC4511M: Leddriver BCD to 7 segment 1 Digit; Manufacturer: TEXAS INSTRUMENTS; Parts: 1; CmpIndex: 55; DXDB_LIBNAME: IC Generic; Level: STD; Max Temp: 125; Min Temp: -55; Ref Designator: U202; SymIndex: 32; Valid: 0
U203 = CD74HC4511M: Leddriver BCD to 7 segment 1 Digit; Manufacturer: TEXAS INSTRUMENTS; Parts: 1; CmpIndex: 75; DXDB_LIBNAME: IC Generic; Level: STD; Max Temp: 125; Min Temp: -55; Ref Designator: U203; SymIndex: 32; Valid: 0
U204 = LM1117MPX: 3.3V/1A fixed regulator; Manufacturer: ON-SEMI; Part Name: 800mA Low-Dropout Linear Regulator, SOT223; CmpIndex: 10; DXDB_LIBNAME: IC Power; Level: STD; Ref Designator: U204; SymIndex: 36; Valid: -1; Vin Max: 18; Vin Min: -0.3; Vout Max: 3.365; Vout Min: 3.235
W200 = ANT-433-SP: 433MHz 50 Ohm Antenna module; Manufacturer: Linx Technologies; CmpIndex: 93; Level: STD; Max Temp: 130; Min Temp: -40; Quality: Q2; Ref Designator: W200; SymIndex: 37; Valid: 0
X200 = M20_9770842: 1x8 pin 2.54 mm pitch vertical header; Manufacturer: HARWIN; Part Name: STD_HEADER_1x8_2.54_THT; CmpIndex: 9; DXDB_LIBNAME: Connector; Gender: male; Level: STD; Ref Designator: X200; SymIndex: 17; Valid: -1
X201 = M20_9770242: 1x2 pin 2.54 mm pitch vertical header; Manufacturer: HARWIN; Part Name: STD_HEADER_1x2_2.54_THT; CmpIndex: 11; DXDB_LIBNAME: Connector; Gender: male; Level: STD; Name: 9V in; Ref Designator: X201; SymIndex: 21; Valid: -1

## Sheet TX.SchDoc
size A2; SheetNumber: 3; SheetTotal: 4; APPROVED: Yes; Border_Classification: ?; CmpIndex: 0; ENGINEER: KuRe/SnLe; REVIEWED: Yes; REVISION: 2.0; SymIndex: 1; SHEET_SIZE: A2
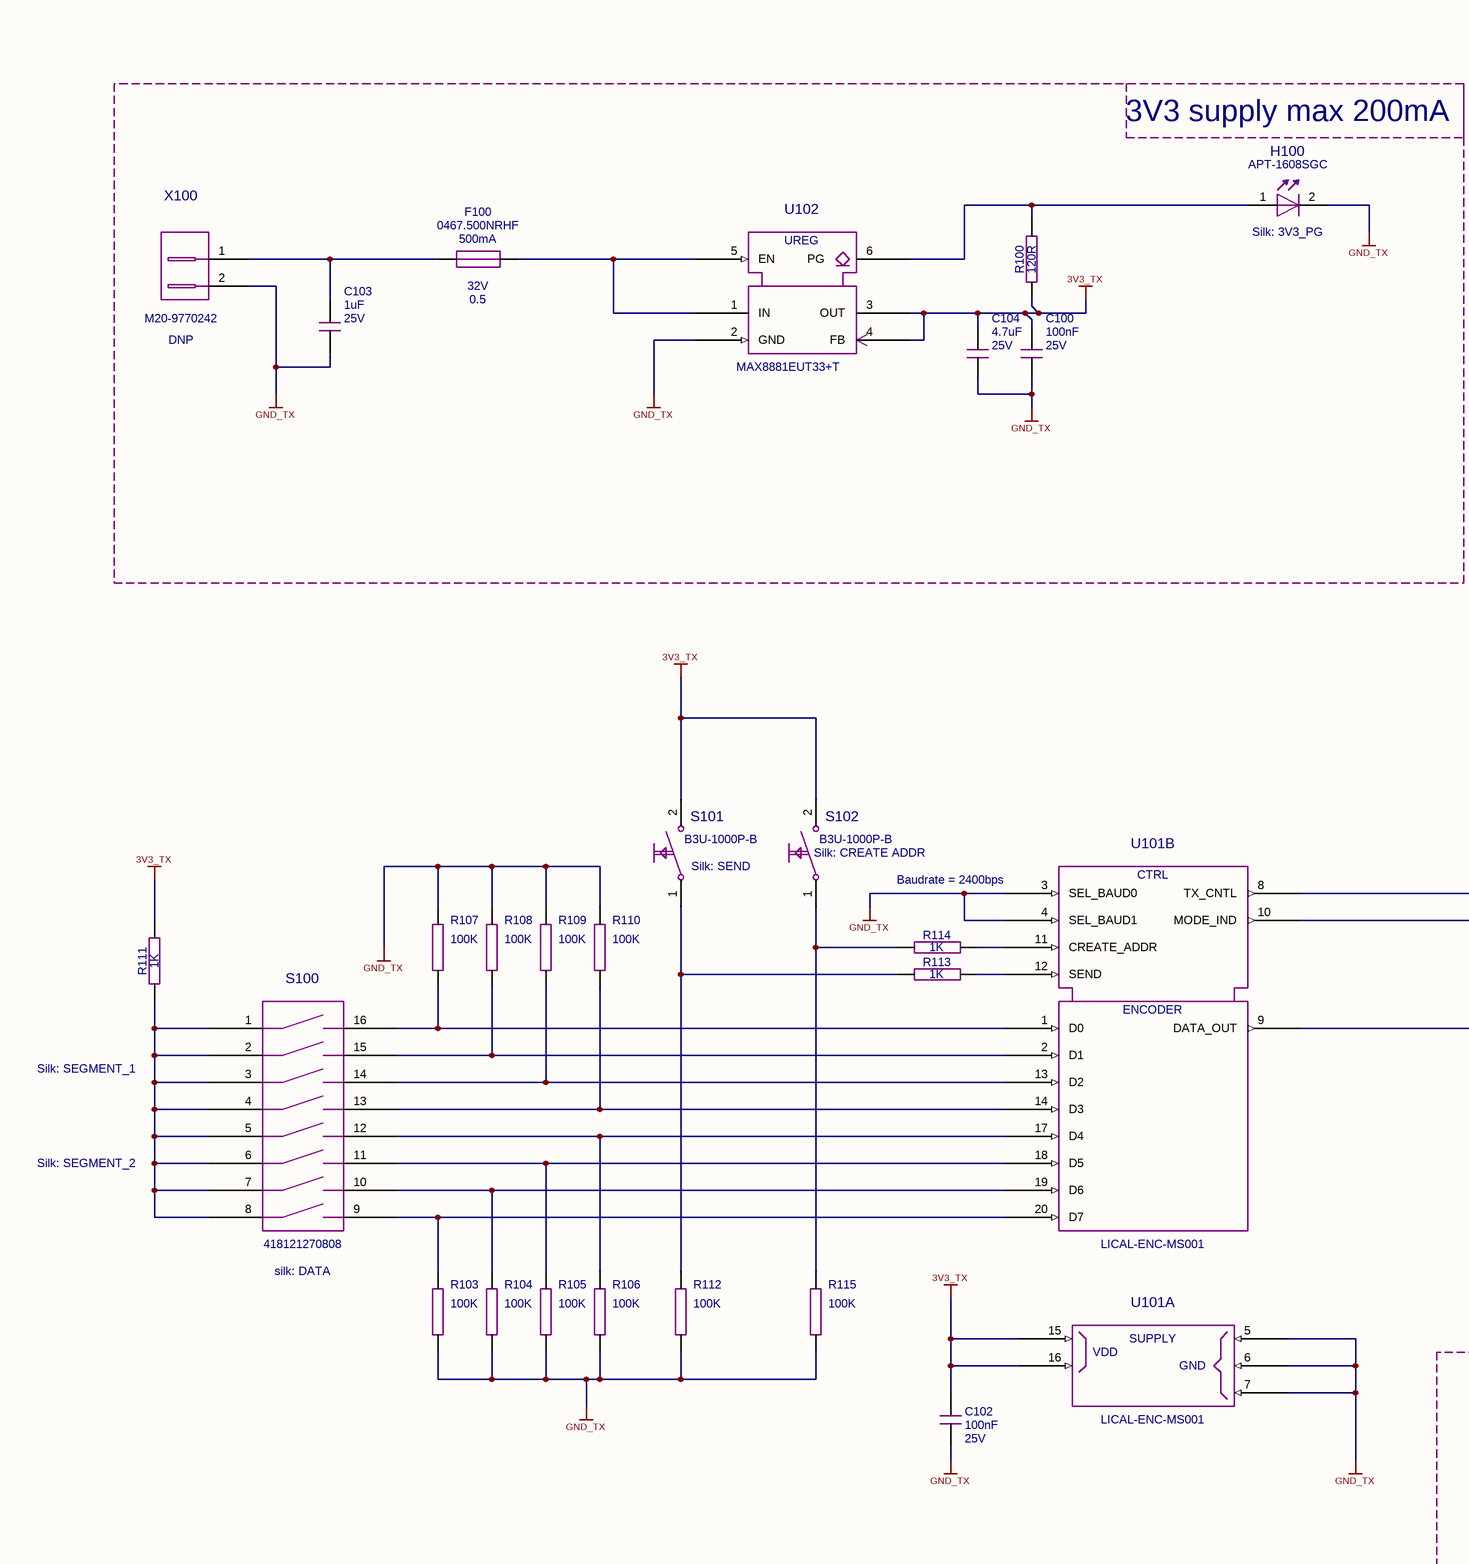
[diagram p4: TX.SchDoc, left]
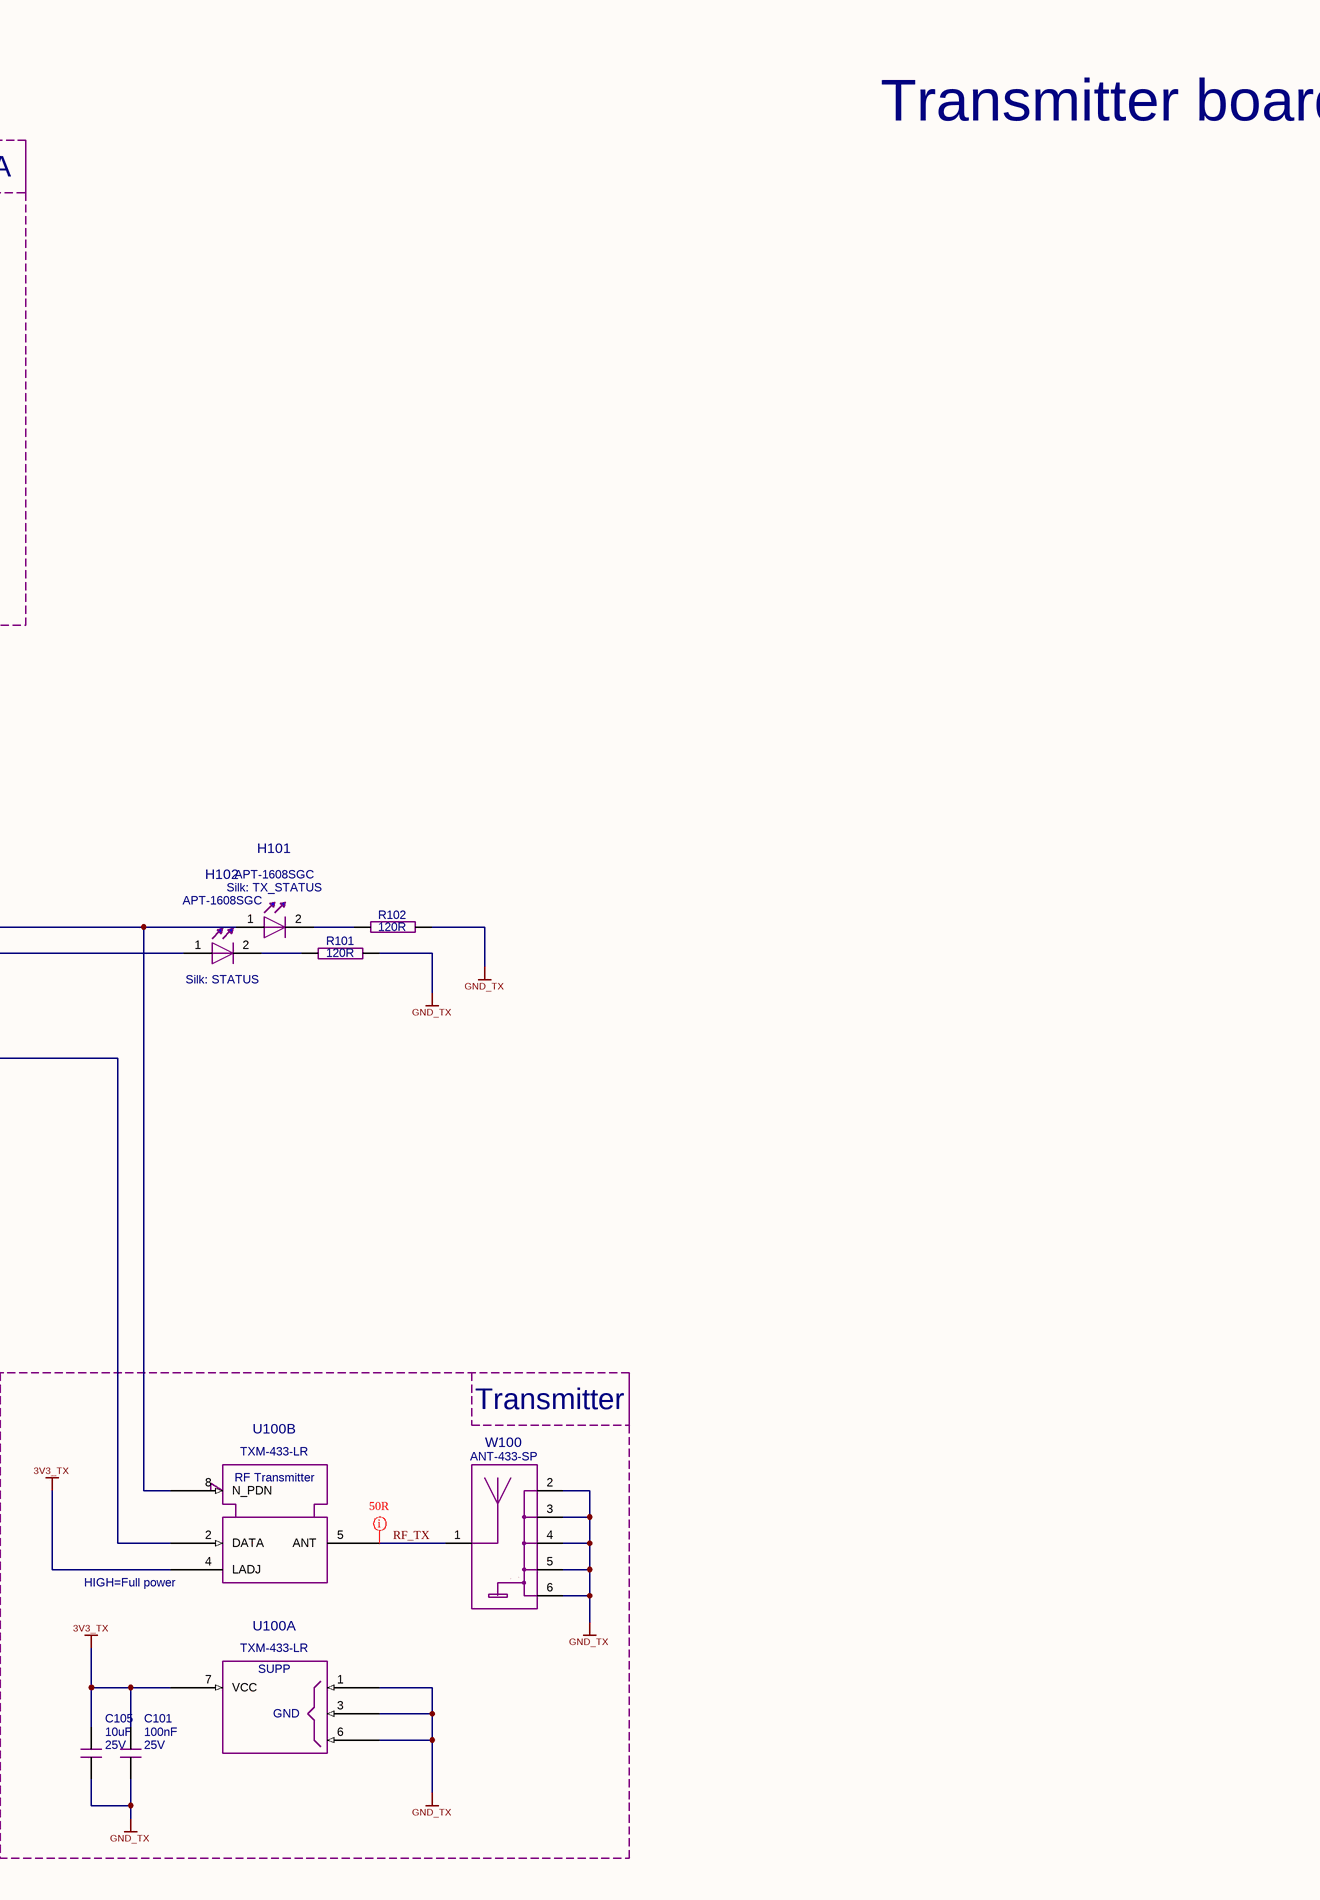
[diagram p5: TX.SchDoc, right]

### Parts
C100  value 100nF  Voltage: 25V  [CAPC1608X90N_0603_GENERIC]  (hidden comment: C_0603_1608X90_GENERIC)
C101  value 100nF  Voltage: 25V  [CAPC1608X90N_0603_GENERIC]  (hidden comment: C_0603_1608X90_GENERIC)
C102  value 100nF  Voltage: 25V  [CAPC1608X90N_0603_GENERIC]  (hidden comment: C_0603_1608X90_GENERIC)
C103  value 1uF  Voltage: 25V  [CAPC2012X150N_0805_GENERIC]  (hidden comment: C_0805_2012X150_GENERIC)
C104  value 4.7uF  Voltage: 25V  [CAPC1608X105N]  (hidden comment: CL10A226MP8NUNE)
C105  value 10uF  Voltage: 25V  [CAPC3216X190N_1206_GENERIC]  (hidden comment: C_1206_3216X190_GENERIC)
F100  value 500mA  Current: 0.5  MPN: 0467.500NRHF  Voltage: 32V  [RESC1608X60N_0603_GENERIC]  (hidden comment: 0467XXXX)
H100  MPN: APT-1608SGC  [LEDC1608X110N]  (hidden comment: KP-1608SGC)
H101  MPN: APT-1608SGC  [LEDC1608X110N]  (hidden comment: KP-1608SGC)
H102  MPN: APT-1608SGC  [LEDC1608X110N]  (hidden comment: KP-1608SGC)
R100  value 120R  [RESC2012X60N_0805_GENERIC]  (hidden comment: R_0805_2012X60_GENERIC)
R101  value 120R  [RESC2012X60N_0805_GENERIC]  (hidden comment: R_0805_2012X60_GENERIC)
R102  value 120R  [RESC2012X60N_0805_GENERIC]  (hidden comment: R_0805_2012X60_GENERIC)
R103  value 100K  [RESC2012X60N_0805_GENERIC]  (hidden comment: R_0805_2012X60_GENERIC)
R104  value 100K  [RESC2012X60N_0805_GENERIC]  (hidden comment: R_0805_2012X60_GENERIC)
R105  value 100K  [RESC2012X60N_0805_GENERIC]  (hidden comment: R_0805_2012X60_GENERIC)
R106  value 100K  [RESC2012X60N_0805_GENERIC]  (hidden comment: R_0805_2012X60_GENERIC)
R107  value 100K  [RESC2012X60N_0805_GENERIC]  (hidden comment: R_0805_2012X60_GENERIC)
R108  value 100K  [RESC2012X60N_0805_GENERIC]  (hidden comment: R_0805_2012X60_GENERIC)
R109  value 100K  [RESC2012X60N_0805_GENERIC]  (hidden comment: R_0805_2012X60_GENERIC)
R110  value 100K  [RESC2012X60N_0805_GENERIC]  (hidden comment: R_0805_2012X60_GENERIC)
R111  value 1K  [RESC2012X60N_0805_GENERIC]  (hidden comment: R_0805_2012X60_GENERIC)
R112  value 100K  [RESC2012X60N_0805_GENERIC]  (hidden comment: R_0805_2012X60_GENERIC)
R113  value 1K  [RESC2012X60N_0805_GENERIC]  (hidden comment: R_0805_2012X60_GENERIC)
R114  value 1K  [RESC2012X60N_0805_GENERIC]  (hidden comment: R_0805_2012X60_GENERIC)
R115  value 100K  [RESC2012X60N_0805_GENERIC]  (hidden comment: R_0805_2012X60_GENERIC)
S100  418121270808  [WE_418121270808]
S101  MPN: B3U-1000P-B  [OMRON_B3U_1000P_B]  (hidden comment: B3U_1000P_B)
S102  MPN: B3U-1000P-B  [OMRON_B3U_1000P_B]  (hidden comment: B3U_1000P_B)
U100  TXM-433-LR  [LINX_TXM-433-LR]  (parts A,B of 2)
U101  LICAL-ENC-MS001  [SOP65P780X200-20N]  (parts A,B of 2)
U102  MPN: MAX8881EUT33+T  [SOT95P280X100-6N]  (hidden comment: MAX8881EU)
W100  ANT-433-SP  [LINX_ANT-433-SP]
X100  MPN: M20-9770242  Place: DNP  [HARWIN_M20_9770242]  (hidden comment: M20_9770242)

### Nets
3V3_TX: C100.1(P) C101.1(P) C102.1(P) C104.1(P) C105.1(P) R100.1(P) R111.2(M) S101.2(S2) S102.2(S2) U100.4(LADJ) U100.7(VCC) U101.15(VDD1) U101.16(VDD2) U102.3(OUT) U102.4(FB)
GND_TX: C100.2(M) C101.2(M) C102.2(M) C103.2(M) C104.2(M) C105.2(M) H100.2(K) R101.2(M) R102.2(M) R103.1(P) R104.1(P) R105.1(P) R106.1(P) R107.2(M) R108.2(M) R109.2(M) R110.2(M) R112.1(P) R115.1(P) U100.1(GND1) U100.3(GND2) U100.6(GND3) U101.3(SEL_BAUD0) U101.4(SEL_BAUD1) U101.5(GND1) U101.6(GND2) U101.7(GND3) U102.2(GND) W100.2(GND1) W100.3(GND2) W100.4(GND3) W100.5(GND4) W100.6(GND5) X100.2(P2)
RF_TX: U100.5(ANT) W100.1(ANT)
NetC103_1: C103.1(P) F100.1(A) X100.1(P1)
NetF100_2: F100.2(B) U102.1(IN) U102.5(EN)
NetH100_1: H100.1(A) R100.2(M) U102.6(PG)
NetH101_1: H101.1(A) U100.8(N_PDN) U101.8(TX_CNTL)
NetH101_2: H101.2(K) R102.1(P)
NetH102_1: H102.1(A) U101.10(MODE_IND)
NetH102_2: H102.2(K) R101.1(P)
NetR103_2: R103.2(M) S100.9(S8_2) U101.20(D7)
NetR104_2: R104.2(M) S100.10(S7_2) U101.19(D6)
NetR105_2: R105.2(M) S100.11(S6_2) U101.18(D5)
NetR106_2: R106.2(M) S100.12(S5_2) U101.17(D4)
NetR107_1: R107.1(P) S100.16(S1_2) U101.1(D0)
NetR108_1: R108.1(P) S100.15(S2_2) U101.2(D1)
NetR109_1: R109.1(P) S100.14(S3_2) U101.13(D2)
NetR110_1: R110.1(P) S100.13(S4_2) U101.14(D3)
NetR111_1: R111.1(P) S100.1(S1_1) S100.2(S2_1) S100.3(S3_1) S100.4(S4_1) S100.5(S5_1) S100.6(S6_1) S100.7(S7_1) S100.8(S8_1)
NetR112_2: R112.2(M) R113.1(P) S101.1(S1)
NetR113_2: R113.2(M) U101.12(SEND)
NetR114_1: R114.1(P) R115.2(M) S102.1(S1)
NetR114_2: R114.2(M) U101.11(CREATE_ADDR)
NetU100_2: U100.2(DATA) U101.9(DATA_OUT)

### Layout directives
net class 50R: RF_TX

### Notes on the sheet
- Transmitter board
- 3V3 supply max 200mA
- (near H100) Silk: 3V3_PG
- (near S101) Silk: SEND
- (near S102) Silk: CREATE ADDR
- Baudrate = 2400bps
- (near H101) Silk: TX_STATUS
- (near H102) Silk: STATUS
- Silk: SEGMENT_1
- Silk: SEGMENT_2
- (near S100) silk: DATA
- Transmitter
- (near U100) HIGH=Full power

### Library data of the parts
C100 = C_0603_1608X90_GENERIC: 100nF 25V 10%; Manufacturer: MURATA; MPN: GRM188R71E104KA01D; Part Name: Ceramic chip capacitor 0603-1608x90, generic; Parts: 1; Capacitance: 100000; CmpIndex: 9; Dielectric: X7R; DXDB_LIBNAME: Capacitor; Level: STD; Ref Designator: C100; SymIndex: 23; Tolerance: 10; Type: Ceramic; Valid: -1
C101 = C_0603_1608X90_GENERIC: 100nF 25V 10%; Manufacturer: MURATA; MPN: GRM188R71E104KA01D; Part Name: Ceramic chip capacitor 0603-1608x90, generic; Parts: 1; Capacitance: 100000; CmpIndex: 36; Dielectric: X7R; DXDB_LIBNAME: Capacitor; Level: STD; Ref Designator: C101; SymIndex: 23; Tolerance: 10; Type: Ceramic; Valid: -1
C102 = C_0603_1608X90_GENERIC: 100nF 25V 10%; Manufacturer: MURATA; MPN: GRM188R71E104KA01D; Part Name: Ceramic chip capacitor 0603-1608x90, generic; Parts: 1; Capacitance: 100000; CmpIndex: 37; Dielectric: X7R; DXDB_LIBNAME: Capacitor; Level: STD; Ref Designator: C102; SymIndex: 23; Tolerance: 10; Type: Ceramic; Valid: -1
C103 = C_0805_2012X150_GENERIC: 1µF 25V 10%; Manufacturer: AVX; MPN: 08053C105K4Z2A; Part Name: Ceramic chip capacitor 0805-2012x150, generic; Parts: 1; Capacitance: 1000000; CmpIndex: 14; Dielectric: X7R; DXDB_LIBNAME: Capacitor; Level: STD; Ref Designator: C103; SymIndex: 23; Tolerance: 10; Type: Ceramic; Valid: -1
C104 = CL10A226MP8NUNE: 4.7uF 25V 10%; Alternate Manufacturer: SAMSUNG; Alternate MPN: CL10A475KA8NQNC; Manufacturer: AVX; MPN: 06033D475KAT2A; Part Name: CAP 22uF 10V 0603 X5R; Parts: 1; Capacitance: 4700000; CmpIndex: 15; Dielectric: X5R; DXDB_LIBNAME: Capacitor; Level: STD; Ref Designator: C104; SymIndex: 23; Tolerance: 10; Type: Ceramic; Valid: 0
C105 = C_1206_3216X190_GENERIC: 10uF 25V 10%; Manufacturer: AVX; MPN: 12063C106KAT2A; Part Name: Cheramic chip capacitor 1206-3216x190, generic; Parts: 1; Capacitance: 10000000; CmpIndex: 45; Dielectric: X7R; DXDB_LIBNAME: Capacitor; Level: STD; Max Temp: +125; Min Temp: -55; Ref Designator: C105; SymIndex: 23; Tolerance: 10; Type: Ceramic; Valid: -1
F100 = 0467XXXX: Thin film 0603 fuse very fast acting; Manufacturer: LITTELFUSE; Part Name: Thin film 0603 very fast acting; CmpIndex: 56; Level: STD; Max Temp: +90; Min Temp: -55; Ref Designator: F100; SymIndex: 25; Valid: -1
H100 = KP-1608SGC: LED Green; Manufacturer: KINGBRIGHT; Part Name: SMD LED lamp, Green; Parts: 1; CmpIndex: 57; Current: 20mA; DXDB_LIBNAME: Diode; Level: STD; Ref Designator: H100; SymIndex: 29; Valid: -1
H101 = KP-1608SGC: LED Green; Manufacturer: KINGBRIGHT; Part Name: SMD LED lamp, Green; Parts: 1; CmpIndex: 11; Current: 20mA; DXDB_LIBNAME: Diode; Level: STD; Ref Designator: H101; SymIndex: 29; Valid: -1
H102 = KP-1608SGC: LED Green; Manufacturer: KINGBRIGHT; Part Name: SMD LED lamp, Green; Parts: 1; CmpIndex: 39; Current: 20mA; DXDB_LIBNAME: Diode; Level: STD; Ref Designator: H102; SymIndex: 29; Valid: -1
R100 = R_0805_2012X60_GENERIC: 0.125W 5% 120R 50V; Manufacturer: YAGEO; MPN: RC0805JR-07120RL; Part Name: resistor_0805-2012x60 generic; CmpIndex: 43; DXDB_LIBNAME: Resistor_0805; Level: STD; Ref Designator: R100; SymIndex: 28; Valid: -1
R101 = R_0805_2012X60_GENERIC: 0.125W 5% 120R 50V; Manufacturer: YAGEO; MPN: RC0805JR-07120RL; Part Name: resistor_0805-2012x60 generic; CmpIndex: 16; DXDB_LIBNAME: Resistor_0805; Level: STD; Ref Designator: R101; SymIndex: 28; Valid: -1
R102 = R_0805_2012X60_GENERIC: 0.125W 5% 120R 50V; Manufacturer: YAGEO; MPN: RC0805JR-07120RL; Part Name: resistor_0805-2012x60 generic; CmpIndex: 38; DXDB_LIBNAME: Resistor_0805; Level: STD; Ref Designator: R102; SymIndex: 28; Valid: -1
R103 = R_0805_2012X60_GENERIC: 0.125W 5% 100K 50V; Manufacturer: YAGEO; MPN: RC0805JR-07100KL; Part Name: resistor_0805-2012x60 generic; CmpIndex: 25; DXDB_LIBNAME: Resistor_0805; Level: STD; Ref Designator: R103; SymIndex: 28; Valid: -1
R104 = R_0805_2012X60_GENERIC: 0.125W 5% 100K 50V; Manufacturer: YAGEO; MPN: RC0805JR-07100KL; Part Name: resistor_0805-2012x60 generic; CmpIndex: 26; DXDB_LIBNAME: Resistor_0805; Level: STD; Ref Designator: R104; SymIndex: 28; Valid: -1
R105 = R_0805_2012X60_GENERIC: 0.125W 5% 100K 50V; Manufacturer: YAGEO; MPN: RC0805JR-07100KL; Part Name: resistor_0805-2012x60 generic; CmpIndex: 27; DXDB_LIBNAME: Resistor_0805; Level: STD; Ref Designator: R105; SymIndex: 28; Valid: -1
R106 = R_0805_2012X60_GENERIC: 0.125W 5% 100K 50V; Manufacturer: YAGEO; MPN: RC0805JR-07100KL; Part Name: resistor_0805-2012x60 generic; CmpIndex: 28; DXDB_LIBNAME: Resistor_0805; Level: STD; Ref Designator: R106; Valid: -1
R107 = R_0805_2012X60_GENERIC: 0.125W 5% 100K 50V; Manufacturer: YAGEO; MPN: RC0805JR-07100KL; Part Name: resistor_0805-2012x60 generic; CmpIndex: 29; DXDB_LIBNAME: Resistor_0805; Level: STD; Ref Designator: R107; SymIndex: 28; Valid: -1
R108 = R_0805_2012X60_GENERIC: 0.125W 5% 100K 50V; Manufacturer: YAGEO; MPN: RC0805JR-07100KL; Part Name: resistor_0805-2012x60 generic; CmpIndex: 30; DXDB_LIBNAME: Resistor_0805; Level: STD; Ref Designator: R108; SymIndex: 28; Valid: -1
R109 = R_0805_2012X60_GENERIC: 0.125W 5% 100K 50V; Manufacturer: YAGEO; MPN: RC0805JR-07100KL; Part Name: resistor_0805-2012x60 generic; CmpIndex: 31; DXDB_LIBNAME: Resistor_0805; Level: STD; Ref Designator: R109; SymIndex: 28; Valid: -1
R110 = R_0805_2012X60_GENERIC: 0.125W 5% 100K 50V; Manufacturer: YAGEO; MPN: RC0805JR-07100KL; Part Name: resistor_0805-2012x60 generic; CmpIndex: 32; DXDB_LIBNAME: Resistor_0805; Level: STD; Ref Designator: R110; SymIndex: 28; Valid: -1
R111 = R_0805_2012X60_GENERIC: Resistor_1K_1%_0805; Manufacturer: MULTICOMP; MPN: MCPWR05FTEW1001; Part Name: resistor_0805-2012x60 generic; CmpIndex: 13; DXDB_LIBNAME: Resistor_0805; Level: STD; Ref Designator: R111; SymIndex: 28; Tolerance: 1%; Valid: -1
R112 = R_0805_2012X60_GENERIC: 0.125W 5% 100K 50V; Manufacturer: YAGEO; MPN: RC0805JR-07100KL; Part Name: resistor_0805-2012x60 generic; CmpIndex: 49; DXDB_LIBNAME: Resistor_0805; Level: STD; Ref Designator: R112; SymIndex: 28; Valid: -1
R113 = R_0805_2012X60_GENERIC: Resistor_1K_1%_0805; Manufacturer: MULTICOMP; MPN: MCPWR05FTEW1001; Part Name: resistor_0805-2012x60 generic; CmpIndex: 47; DXDB_LIBNAME: Resistor_0805; Level: STD; Ref Designator: R113; SymIndex: 28; Tolerance: 1%; Valid: -1
R114 = R_0805_2012X60_GENERIC: Resistor_1K_1%_0805; Manufacturer: MULTICOMP; MPN: MCPWR05FTEW1001; Part Name: resistor_0805-2012x60 generic; CmpIndex: 50; DXDB_LIBNAME: Resistor_0805; Level: STD; Ref Designator: R114; SymIndex: 28; Tolerance: 1%; Valid: -1
R115 = R_0805_2012X60_GENERIC: 0.125W 5% 100K 50V; Manufacturer: YAGEO; MPN: RC0805JR-07100KL; Part Name: resistor_0805-2012x60 generic; CmpIndex: 52; DXDB_LIBNAME: Resistor_0805; Level: STD; Ref Designator: R115; SymIndex: 28; Valid: -1
S100 = 418121270808: Dip Switch SPST 8 Position Surface Mount Slide (Standard) Actuator 25mA 24VDC; Manufacturer: WURTH ELEKTRONIK; CmpIndex: 1; Contacts: 8; Level: STD; Max Temp: 85; Min Temp: -40; Ref Designator: S100; SymIndex: 7; Valid: -1; Voltage: 24
S101 = B3U_1000P_B: Ultra-small Tactile Switch; Manufacturer: OMRON; CmpIndex: 2; Level: STD; Max Temp: 0; Ref Designator: S101; SymIndex: 8
S102 = B3U_1000P_B: Ultra-small Tactile Switch; Manufacturer: OMRON; CmpIndex: 51; Contacts: 2; Level: STD; Max Temp: 0; Ref Designator: S102; SymIndex: 8
U100 = TXM-433-LR: LR Series Transmitter, Low Voltage, Low Power; Manufacturer: Linx Technologies; CmpIndex: 4; DXDB_LIBNAME: Module; Level: STD; Max Temp: 85; Min Temp: -40; Quality: Q2; Ref Designator: U100; SymIndex: 10; Valid: 0
U101 = LICAL-ENC-MS001: MS Series Remote Controler Encoder, Low Voltage, Low Power; Manufacturer: LINX TECHNOLOGIES; CmpIndex: 6; DXDB_LIBNAME: IC Generic; Level: STD; Max Temp: 85; Min Temp: -40; Ref Designator: U101; SymIndex: 19; Valid: 0
U102 = MAX8881EU: Low Dropout Linear Regulator with enable and power good, 3.3V, 6 pin SOT23; Manufacturer: MAXIM; Part Name: Low Dropout Linear Regulator, 6 pin SOT23; CmpIndex: 8; DXDB_LIBNAME: IC Power; Level: STD; Max Temp: 85; Min Temp: -40; Output Current: 0.20A; Quality: Q2; Ref Designator: U102; SymIndex: 20; Valid: 0; Vin Max: 12V; Vin Min: 4.3V; Vout Max: 3.3
W100 = ANT-433-SP: 433MHz 50 Ohm Antenna module; Manufacturer: Linx Technologies; CmpIndex: 55; Level: STD; Max Temp: 130; Min Temp: -40; Quality: Q2; Ref Designator: W100; SymIndex: 37; Valid: 0
X100 = M20_9770242: 1x2 pin 2.54 mm pitch vertical header; Manufacturer: HARWIN; Part Name: STD_HEADER_1x2_2.54_THT; CmpIndex: 7; DXDB_LIBNAME: Connector; Gender: male; Level: STD; Name: 9V in; Ref Designator: X100; SymIndex: 21; Valid: -1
